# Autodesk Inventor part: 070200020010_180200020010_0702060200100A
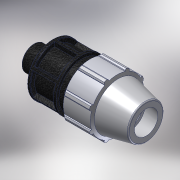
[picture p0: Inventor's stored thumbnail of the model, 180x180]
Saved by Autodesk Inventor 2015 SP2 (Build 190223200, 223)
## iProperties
Created: 2017-02
Part Number: 070200020010_180200020010_0702060200100A
Material: PVC-Piping
Description: PLASSON MALE ADAPTOR 20-1"
Document SubType Name: Modeling
Designer: KIM
Mass: 92.6774 g
Surface Area: 199.44 cm^2
Volume: 66.1981 cm^3
Density: 1.4 g/cm^3
Appearance: PTFE
Author: KIM
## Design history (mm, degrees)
derived "07020.ipt"
feature "Solid1::07020.ipt"
tag "TaggingFeature1"
body "Solid1"
other parameters: "d4" = 12.28571, "d5" = 21.5, "d7" = 48, "d8" = 36, "d9" = 12.28571, "d11" = 2.45714, "d12" = 38.4, "d13" = 120 deg, "d15" = 12 deg, "d16" = 43.2, "d18" = 1, "d19" = 35 deg, "d20" = 17.5 deg, "d21" = 44.64, "d23" = 0, "d25" = 360 deg, "d27" = 0.96, "d34" = 2.4, "d36" = 0, "d42" = 21.5, "d43" = 1.44, "d46" = 0.6, "d49" = 52, "d51" = 86, "d53" = 0.4, "d55" = 360 deg, "d57" = 33.249, "d58" = 16.6245, "d59" = 17.2, "E_" = 48, "H_" = 86, "l_" = 52, "R_" = 33.249
